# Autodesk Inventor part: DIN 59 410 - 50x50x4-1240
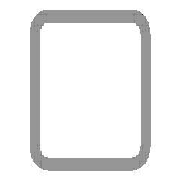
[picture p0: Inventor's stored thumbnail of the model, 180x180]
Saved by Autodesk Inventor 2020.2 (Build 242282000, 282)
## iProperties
Manager: www.cadconsulting.pl
Company: Fabian Stasiak CAD Consulting
IsCustomPart: 1
_CCFamilyMember: 40
_CCFamilyDisplayName: DIN 59410 (Kwadrat) - Rurki stalowe o przekroju kwadratowym formowane na gorąco
_FrameMemberDoc: Frame Member File
_Version: 15.0.0
_GetPNFromCC: 1
Created: 2015-01
Part Number: DIN 59 410 - 50x50x4-1240
Material: Stal, miękka
Description: Rurki stalowe o przekroju kwadratowym formowane na gorąco
Document SubType Name: Modellieren
Standard: DIN
Designer: F.Stasiak
Standards Organization: DIN
Language: pl-PL
Size Designation: 50x50x4
Categories: <MemberInstance><Categories><Category DisplayName="Kształtowniki konstrukcyjne" InternalName="089c4875-fa83-4c05-b084-43b9cc11f5ed" Mnemonic="GRDR"><CategoryPar
Stock Number: 50x50x4
Density: 7.85 g/cm^3
Appearance: Częściowo polerowana
Mass: 6817.69 g
Surface Area: 4356.37 cm^2
Volume: 868.496 cm^3
Catalog Web Link: www.expertbooks.pl
G_W: 50,000 mm
G_H: 50,000 mm
+BD22D635-0862-4ED7-A4CA-62C603390CA0+CUTDETAIL2: Wytnij
+5BC96441-BBE8-4AF1-9985-3B583943D745+CUTDETAIL3: Kąt cięcia 90,00 deg
G_L: 1240,000 mm
Author: F.Stasiak
Subject: Zbiór ćwiczeń. Autodesk Inventor 2020. Kurs Professional
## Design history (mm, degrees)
node "Płaszczyzna początkowa"
node "Płaszczyzna końcowa"
sketch "Szkic1"
  geometry: L1 (-17, 25)-(17, 25); L2 (25, 17)-(25, -17); L3 (17, -25)-(-17, -25); L4 (-25, -17)-(-25, 17); L5 (-37.32, 0)-(37.32, 0) reference; L6 (0, -37.32)-(0, 37.32) reference; L7 (-17, 21)-(17, 21); L8 (21, 17)-(21, -17); L9 (17, -21)-(-17, -21); L10 (-21, -17)-(-21, 17); A1 r 8 centre (-17, 17) between (-17, 25) and (-25, 17); A2 r 8 centre (17, 17) between (25, 17) and (17, 25); A3 r 8 centre (17, -17) between (17, -25) and (25, -17); A4 r 8 centre (-17, -17) between (-25, -17) and (-17, -25); A5 r 4 centre (-17, 17) between (-17, 21) and (-21, 17); A6 r 4 centre (17, 17) between (21, 17) and (17, 21); A7 r 4 centre (17, -17) between (17, -21) and (21, -17); A8 r 4 centre (-17, -17) between (-21, -17) and (-17, -21); 3 further points
  constraints: 16 end point, 16 point on circle, 8 centre point, 8 tangent, 6 point on line, 4 parallel, 3 equal radius, 3 perpendicular, 1 horizontal, 7 other
  dimensions: "b" = 50 distance of point (-25, 25) point (25, 25); "msp_r" = 8 radius of A1 (= 2 x ParT); "d8" = 25 distance between parallel lines of L4 L6 (= d9); "d9" = 25 distance between parallel lines of L3 L5 (= 0.5 x b); "d10" = 4 distance between parallel lines of L3 L9 (= ParT)
extrude "Bryła" new body sketch "Szkic1" taper "d4" = 0 deg; stored distance "NLG" = 10
node "Driven Length"
  sketch "Sketch2"
    geometry: L1 (0, 0)-(10, 0) reference
    constraints: 2 end point, 1 horizontal
  workplane "Work Plane3"
  sketch "Sketch3"
    geometry: L1 (-2, 25)-(12, 25) reference; L2 (-2, 1265)-(12, 1265) reference
    dimensions: "d14" = 1240 distance between parallel lines of L1 L2 (derived)
node "Płaszczyzna konstrukcyjna5"
feature "Podział2"
node "Płaszczyzna konstrukcyjna6"
feature "Podział3"
body "Solid1"
other parameters: "ParT" = 4, "G_OFFSET_START" = -25 [user parameter; used in 1 equation term], "G_OFFSET_END" = -35 [user parameter; used in 1 equation term], "d11" = 25 (= -G_OFFSET_START), "d12" = 1265 (= G_OFFSET_END + B_L), "G_L" = 1240 (= d14) [user parameter], "d13" = 90 deg
